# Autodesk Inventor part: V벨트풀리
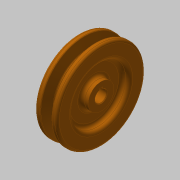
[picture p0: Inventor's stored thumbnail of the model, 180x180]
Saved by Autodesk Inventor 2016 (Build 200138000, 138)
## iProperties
Created: 2015-11
Part Number: V벨트풀리
Material: 알루미늄 6061
Document SubType Name: Modeling
Designer: mduedu
Density: 1 g/cm^3
Appearance: 주황색
Author: mduedu
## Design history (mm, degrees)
sketch "스케치1"
  geometry: L1 (-9.5, 0)-(9.5, 0); L2 (0, 0)-(0, 37.7); L3 (-4.825, 37.7)-(-9.5, 37.7); L4 (-9.5, 37.7)-(-9.5, 0); L5 (0, 28.7)-(-2.074, 28.7); L6 (-2.074, 28.7)-(-4.825, 37.7); L7 (4.825, 37.7)-(9.5, 37.7); L8 (9.5, 37.7)-(9.5, 0); L9 (0, 28.7)-(2.074, 28.7); L10 (2.074, 28.7)-(4.825, 37.7); L11 (-9.5, 35)-(9.5, 35); 3 further points
  constraints: 22 end point, 7 point on line, 4 perpendicular, 3 symmetric about line, 1 coincident, 1 horizontal, 1 horizontal alignment, 1 midpoint, 1 vertical
  dimensions: "d0" = 19 distance of L1.start L1.end; "d2" = 75.4 diameter of L2.end L1 (derived); "d3" = 34 deg angle of L10 L6; "d4" = 6.3 distance between parallel lines of L11 L9; "d5" = 2.7 distance between parallel lines of L7 L11; "d6" = 8 distance of point (4, 35) point (-4, 35); "d7" = 70 diameter of L11 L1
revolve "회전1" sketch "스케치1" stored, may be unused: angle "d8" = 90 deg
sketch "스케치2"
  geometry: C1 r 24 at (0, 0); C2 r 11 at (0, 0); 1 further point
  constraints: 2 centre point, 2 coincident
  dimensions: "d9" = 48 diameter of C1; "d10" = 22 diameter of C2
extrude "돌출1" cut sketch "스케치2" distance "d11" = 6; taper "d12" = 0 deg
fillet "모깎기1" dims "d13" = 3
fillet "모깎기2" dims "d14" = 3
fillet "모깎기3" dims "d15" = 1, "d16" = 0.5, "d17" = 2
hole "구멍1" diameter "d20" = 10; stored, may be unused: countersink angle "d24" = 90 deg, drill point angle "d26" = 118 deg; dims "d18" = 10, "d19" = 10, "d21" = 6, "d22" = 4, "d23" = 2, "d25" = 8
sketch "스케치3"
  geometry: L1 (-1.5, 0)-(1.5, 0); L2 (1.5, 0)-(1.5, 6.4); L3 (1.5, 6.4)-(-1.5, 6.4); L4 (-1.5, 6.4)-(-1.5, 0); 2 further points
  constraints: 8 end point, 2 parallel, 1 coincident, 1 horizontal, 1 midpoint, 1 perpendicular
  dimensions: "d27" = 3 distance of L2.end L3.end; "d29" = 6.4 distance of L3.end L1.start
extrude "돌출2" cut sketch "스케치3" stored distance "d30" = 6; taper "d31" = 0 deg
chamfer "모따기1" distance "d32" = 0.5; stored, may be unused: second distance "d33" = 2, angle "d34" = 45 deg
node "솔리드1"
mirror "대칭1"
